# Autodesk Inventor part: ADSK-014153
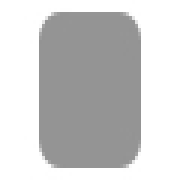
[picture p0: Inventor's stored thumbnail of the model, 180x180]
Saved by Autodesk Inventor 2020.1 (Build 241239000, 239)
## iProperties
Created: 2019-01
Part Number: ADSK-014153
Material: Stahl, weich
Document SubType Name: Modeling
Designer: lutzd
Language: de-DE
Size Designation: 5 x 39,384472 x 39,384472
Categories: <MemberInstance><Categories><Category DisplayName="Sonstige Bauteile" InternalName="5aa15e00-363f-49f2-933f-16f664388e3f" Mnemonic="OTHER"><Category DisplayName
Mass: 60.0398 g
Surface Area: 38.0412 cm^2
Volume: 7.64838 cm^3
Density: 7.85 g/cm^3
Appearance: Halbpoliert
Dimensions: 39,4x39,4x5 mm
Mass: 0,06 kg
DocNumber: ADSK-014153
Folder: 01 - Themengebiete\Simplification\01 - Packaging machine\
VDS_Category: 3D Komponenten
VDS_NumSchm: Autodesk
IsCustomPart: 1
Title: end cap
Author: lutzd
Revision Number: -
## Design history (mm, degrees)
sketch "Sketch1"
  geometry: L1 (0, 20.175)-(0, -21.446); L2 (-20.203, 0)-(20.169, 0); L3 (-19.692, 19.692)-(19.692, 19.692); L4 (19.692, 19.692)-(19.692, -19.692); L5 (19.692, -19.692)-(-19.692, -19.692); L6 (-19.692, -19.692)-(-19.692, 19.692); 1 further point
  constraints: 12 end point, 2 horizontal, 2 parallel, 2 point on line, 1 perpendicular, 1 vertical
  dimensions: "d0" = 39.38447 distance between parallel lines of L5 L3 (= height); "d1" = 19.69224 distance between parallel lines of L2 L3 (= 0.5 x height); "d2" = 39.38447 distance between parallel lines of L6 L4 (= width); "d3" = 19.69224 distance between parallel lines of L6 L1 (= 0.5 x width)
extrude "Extrusion1" new body sketch "Sketch1" distance "d4" = 5 (= thickness); taper "d5" = 0 deg
fillet "Fillet1" dims "d6" = 5 (= fillet), "d7" = 0, "fillet" = 5 [user parameter; used in 1 equation term]
chamfer "Chamfer1" distance "d8" = 0 (computed from chamfer); stored, may be unused: second distance "d9" = 2, angle "d10" = 45 deg; dims "d11" = 0, "chamfer" = 0 [user parameter; used in 1 equation term]
body "Solid1"
other parameters: "thickness" = 5 [user parameter; used in 1 equation term], "width" = 39.38447 [user parameter; used in 2 equation terms], "height" = 39.38447 [user parameter; used in 2 equation terms]
